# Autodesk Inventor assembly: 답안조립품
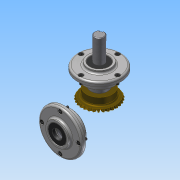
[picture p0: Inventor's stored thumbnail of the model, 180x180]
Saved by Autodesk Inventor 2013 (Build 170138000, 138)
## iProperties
Created: 2015-07
Part Number: 답안조립품
Document SubType Name: Assembly
Designer: Administrator
Author: Administrator
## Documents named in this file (10)
- C:\Users\Administrator\Desktop\450706V1019\답안조립품.iam
- C:\Users\Administrator\Desktop\450706V1019\1-본체.ipt
- C:\Users\Administrator\Desktop\450706V1019\커버.ipt
- C:\Users\Administrator\Desktop\450706V1019\오일실.ipt
- C:\Users\Administrator\Desktop\450706V1019\M4.ipt
- C:\Users\Administrator\Desktop\450706V1019\베어링 6203.ipt
- C:\Users\Administrator\Desktop\450706V1019\메인 축.ipt
- 메인 축.ipt
- C:\Users\Administrator\Desktop\450706V1019\키 5x5.ipt
- C:\Users\Administrator\Desktop\450706V1019\메인 베벨기어.ipt
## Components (9 placed, 2 different names)
1. 1-본체:1
2. M4:1
3. M4:2
4. M4:3
5. M4:4
6. M4:5
7. M4:6
8. M4:7
9. M4:8
